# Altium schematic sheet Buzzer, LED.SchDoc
size Letter; Organization: Cegep Limoilou; Address1: 1300, 8e Avenue; Address2: Québec, QC; Address3: Canada; Address4: G1J 5L5; Revision: Enseignants; SheetNumber: 3; SheetTotal: 4; Conception: Ilyes Gharmoul; Titre: Buzzer LED Conn; Modification: Ilyes G
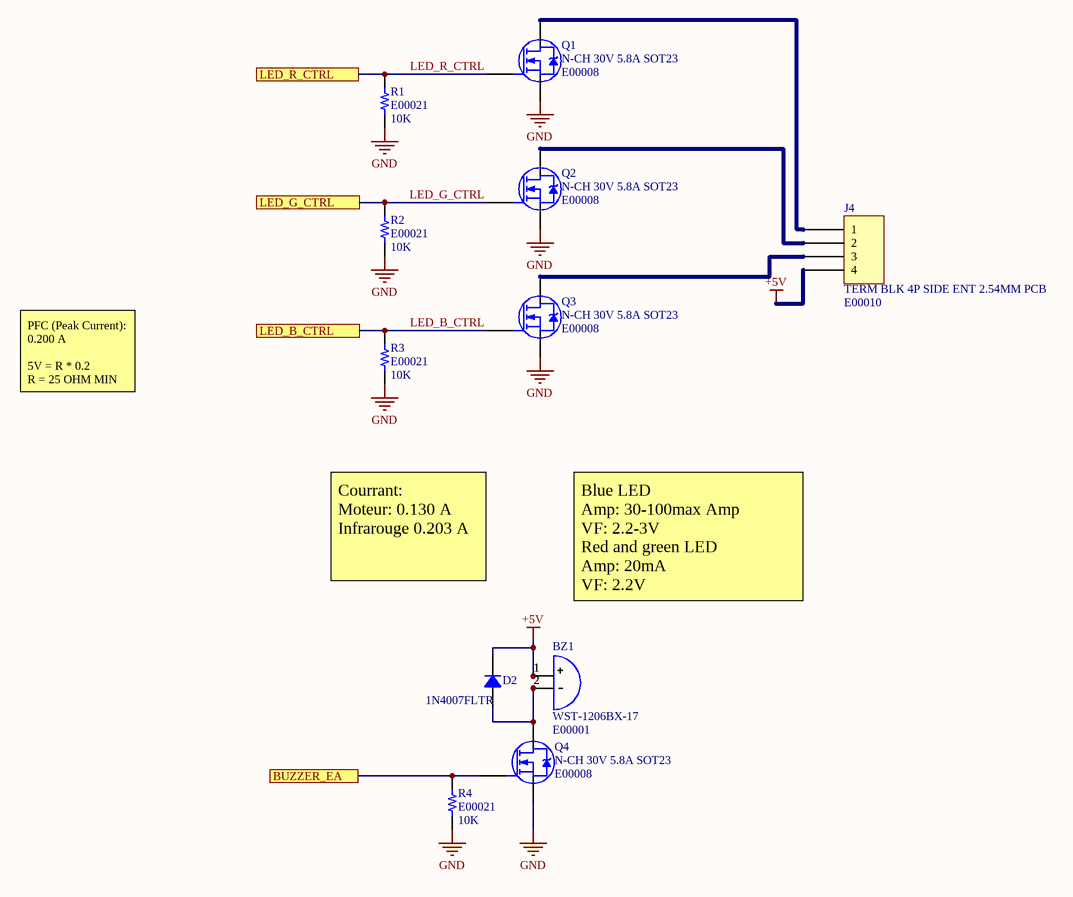
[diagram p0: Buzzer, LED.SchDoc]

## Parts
BZ1  WST-1206BX-17  ADAM Inventory Number 1: E00001  [BUZZ WST-1206BX]
D2  1N4007FLTR  [SOD123F]
J4  TERM BLK 4P SIDE ENT 2.54MM PCB  ADAM Inventory Number 1: E00010  [TERM BLOC 4P]
Q1  N-CH 30V 5.8A SOT23  ADAM Inventory Number 1: E00008  [N-CHANNEL TRANS]
Q2  N-CH 30V 5.8A SOT23  ADAM Inventory Number 1: E00008  [N-CHANNEL TRANS]
Q3  N-CH 30V 5.8A SOT23  ADAM Inventory Number 1: E00008  [N-CHANNEL TRANS]
Q4  N-CH 30V 5.8A SOT23  ADAM Inventory Number 1: E00008  [N-CHANNEL TRANS]
R1  ADAM Inventory Number 1: E00021  [RES 0603]  (hidden comment: 10K)
R2  ADAM Inventory Number 1: E00021  [RES 0603]  (hidden comment: 10K)
R3  ADAM Inventory Number 1: E00021  [RES 0603]  (hidden comment: 10K)
R4  ADAM Inventory Number 1: E00021  [RES 0603]  (hidden comment: 10K)

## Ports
BUZZER_EA, LED_B_CTRL, LED_G_CTRL, LED_R_CTRL

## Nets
+5V: BZ1.1 D2.2 J4.4
GND: Q1.2(S) Q2.2(S) Q3.2(S) Q4.2(S) R1.1 R2.1 R3.1 R4.1
BUZZER_EA: Q4.1(G) R4.2 ; port BUZZER_EA
LED_B_CTRL: Q3.1(G) R3.2 ; port LED_B_CTRL
LED_G_CTRL: Q2.1(G) R2.2 ; port LED_G_CTRL
LED_R_CTRL: Q1.1(G) R1.2 ; port LED_R_CTRL
NetBZ1_2: BZ1.2 D2.1 Q4.3(D)
NetJ4_1: J4.1 Q1.3(D)
NetJ4_2: J4.2 Q2.3(D)
NetJ4_3: J4.3 Q3.3(D)

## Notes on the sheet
- PFC (Peak Current): 0.200 A
  5V = R * 0.2
  R = 25 OHM MIN
- Courrant:
  Moteur: 0.130 A
  Infrarouge 0.203 A
- Blue LED
  Amp: 30-100max Amp
  VF: 2.2-3V
  Red and green LED
  Amp: 20mA
  VF: 2.2V

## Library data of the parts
BZ1 = WST-1206BX-17: Buzzers Indicator, Internally Driven Magnetic 5 V 30mA 3.1kHz 83dB @ 5V, 10cm Through Hole PC Pins
D2 = 1N4007FLTR: STANDARD RECTIFIER 1000V SOD-123; Manufacturer: SMC Diode Solutions; Capacitance @ Vr, F: 15pF @ 4V, 1MHz; Current - Average Rectified (Io): 1A; Current - Reverse Leakage @ Vr: 5µA @ 1000V; Speed: Standard Recovery >500ns, > 200mA (Io); Voltage - Forward (Vf) (Max) @ If: 1.1V @ 1A
J4 = TERM BLK 4P SIDE ENT 2.54MM PCB: Manufacturer Part Number 1: 282834-4; Manufacturer: TE Connectivity AMP Connectors; Current: 10A; Mating Orientation: Horizontal with Board; Number of Levels: 1; Pitch: 0.100" (2.54mm); Positions Per Level: 4; Voltage: 150V; Wire Gauge: 16-30 AWG; Wire Termination: Screw - Rising Cage Clamp
Q1-Q4 = TRANS N-CHANNEL 30V 5.8A SOT23: N-Channel 5.8A (Tj) 350mW Surface Mount SOT-23; Manufacturer: MCC; Manufacturer Part Number 1: SI3404-TP
R1-R4 = RES SMD 10K OHM: RES SMD 10K OHM 1% 1/10W 0603; Manufacturer Part Number 1: RC0603FR-0710KL; Manufacturer: Rohm Semiconductor; Power (Watts): 0.25W, 1/4W; Temperature Coefficient: ±100ppm/°C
